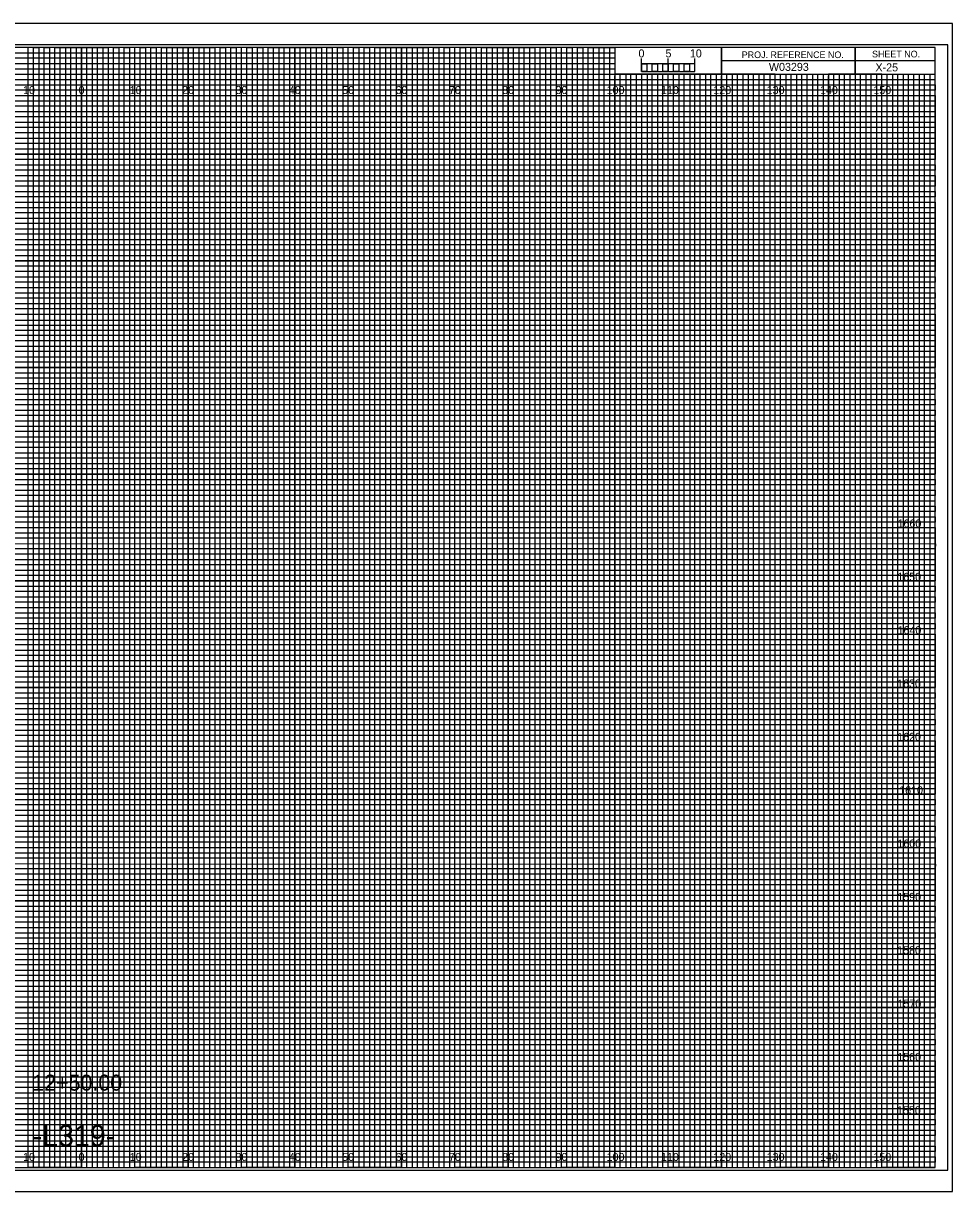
# Model space of a CAD drawing. Extents: x -13 to 323, y 215 to 434.
# Drawn here: x 149.1 to 323.3, y 215.5 to 434.5 of the extents above; entities that cross this region are included whole.
import ezdxf

# ---------------------------------------------------------------- set-up
doc = ezdxf.new("R2010")
doc.units = 0
for name, color, linetype in [('Exist Cross Section Cell', 7, 'Continuous'), ('Exist XS Center Line Elevation Label', 7, 'Continuous'), ('Exist XS Ground Line', 7, 'Continuous'), ('Prop XS EOT Tick Mark', 7, 'Continuous'), ('Prop XS Finish Grade', 7, 'Continuous'), ('Prop XS Finish Grade Earthwork', 7, 'Continuous'), ('Prop XS Finish Grade Pavement', 7, 'Continuous'), ('Prop XS Pvmt Edge Slope', 7, 'Continuous'), ('Prop XS SE Text', 7, 'Continuous'), ('Prop XS Side Slope Text', 7, 'Continuous'), ('Prop XS SS Elevation Text', 7, 'Continuous'), ('Prop XS Subgrade Earthwork', 7, 'Continuous'), ('Prop XSC Text', 7, 'Continuous'), ('Scratch_Level_5', 7, 'Continuous'), ('Typical Curb CELL', 7, 'Continuous'), ('Typical Guardrail CELL', 7, 'Continuous')]:
    doc.layers.add(name, color=color, linetype=linetype)

msp = doc.modelspace()

# ---------------------------------------------------------------- linework, layer by layer
at = {"layer": 'Exist Cross Section Cell'}
for points in [[(145, 220), (155, 220), (155, 430), (165, 430), (165, 220), (175, 220), (175, 430), (185, 430), (185, 220), (195, 220), (195, 430), (205, 430), (205, 220), (215, 220), (215, 430), (225, 430), (225, 220), (235, 220), (235, 430), (245, 430), (245, 220), (255, 220), (255, 430), (259.93, 430), (260, 430), (260, 425), (264.99, 425), (264.99, 220), (275, 220), (275, 425), (285, 425), (285, 220), (295, 220), (295, 425), (305, 425), (305, 220), (315, 220), (315, 425)], [(0, 425), (275, 425)], [(0, 405), (320, 405), (320, 415), (0, 415)], [(0, 385), (320, 385), (320, 395), (0, 395)], [(0, 365), (320, 365), (320, 375), (0, 375)], [(0, 345), (320, 345), (320, 355), (0, 355)], [(0, 325), (320, 325), (320, 335), (0, 335)], [(0, 305), (320, 305), (320, 315), (0, 315)], [(0, 285), (320, 285), (320, 295), (0, 295)], [(0, 265), (320, 265), (320, 275), (0, 275)], [(0, 245), (320, 245), (320, 255), (0, 255)], [(0, 225), (320, 225), (320, 235), (0, 235)]]:
    msp.add_lwpolyline(points, dxfattribs=at)
at = {"layer": 'Exist XS Center Line Elevation Label'}
for p, q in [((150, 430), (140, 430)), ((150, 220), (150, 430)), ((170, 430), (160, 430)), ((160, 430), (160, 220)), ((170, 220), (170, 430)), ((190, 430), (180, 430)), ((180, 430), (180, 220)), ((190, 220), (190, 430)), ((210, 430), (200, 430)), ((200, 430), (200, 220)), ((210, 220), (210, 430)), ((230, 430), (220, 430)), ((220, 430), (220, 220)), ((230, 220), (230, 430)), ((250, 430), (240, 430)), ((240, 430), (240, 220)), ((250, 220), (250, 430)), ((260, 430), (260, 220)), ((270, 220), (270, 425)), ((290, 425), (280, 425)), ((280, 425), (280, 220)), ((290, 220), (290, 425)), ((310, 425), (300, 425)), ((300, 425), (300, 220)), ((310, 220), (310, 425)), ((160, 220), (150, 220)), ((180, 220), (170, 220)), ((200, 220), (190, 220)), ((220, 220), (210, 220)), ((240, 220), (230, 220)), ((260, 220), (250, 220)), ((280, 220), (270, 220)), ((300, 220), (290, 220)), ((320, 220), (310, 220)), ((320, 220), (320, 220))]:
    msp.add_line(p, q, dxfattribs=at)
for points in [[(0, 420), (320, 420), (320, 410), (0, 410)], [(0, 400), (320, 400), (320, 390), (0, 390)], [(0, 380), (320, 380), (320, 370), (0, 370)], [(0, 360), (320, 360), (320, 350), (0, 350)], [(0, 340), (320, 340), (320, 330), (0, 330)], [(0, 320), (320, 320), (320, 310), (0, 310)], [(0, 300), (320, 300), (320, 290), (0, 290)], [(0, 280), (320, 280), (320, 270), (0, 270)], [(0, 260), (320, 260), (320, 250), (0, 250)], [(0, 240), (320, 240), (320, 230), (0, 230)]]:
    msp.add_lwpolyline(points, dxfattribs=at)
at = {"layer": 'Prop XS Finish Grade'}
msp.add_lwpolyline([(-10.8, 219.5), (322.4, 219.5), (322.4, 430.5), (-10.8, 430.5)], close=True, dxfattribs=at)
at = {"layer": 'Prop XS Finish Grade Earthwork'}
for p, q in [((150, 220), (150, 430)), ((160, 220), (160, 430)), ((170, 220), (170, 430)), ((180, 220), (180, 430)), ((190, 220), (190, 430)), ((200, 220), (200, 430)), ((210, 220), (210, 430)), ((220, 220), (220, 430)), ((230, 220), (230, 430)), ((240, 220), (240, 430)), ((250, 220), (250, 430)), ((260, 220), (260, 424.69)), ((270, 220), (270, 424.69)), ((280, 220), (280, 424.69)), ((290, 220), (290, 424.69)), ((300, 220), (300, 424.69)), ((310, 220), (310, 424.69)), ((0, 420), (320, 420)), ((0, 410), (320, 410)), ((0, 400), (320, 400)), ((0, 390), (320, 390)), ((0, 380), (320, 380)), ((0, 370), (320, 370)), ((0, 360), (320, 360)), ((0, 350), (320, 350)), ((0, 340), (320, 340)), ((0, 330), (320, 330)), ((0, 320), (320, 320)), ((0, 310), (320, 310)), ((0, 300), (320, 300)), ((0, 290), (320, 290)), ((0, 280), (320, 280)), ((0, 270), (320, 270)), ((0, 260), (320, 260)), ((0, 250), (320, 250)), ((0, 240), (320, 240)), ((0, 230), (320, 230))]:
    msp.add_line(p, q, dxfattribs=at)
at = {"layer": 'Prop XS Finish Grade Pavement'}
for p, q in [((267, 425), (266.01, 425)), ((266.01, 425), (266.01, 220)), ((267, 220), (267, 425)), ((269, 425), (268, 425)), ((268, 425), (268, 220)), ((269, 220), (269, 425)), ((266.01, 220), (265, 220)), ((268, 220), (267, 220))]:
    msp.add_line(p, q, dxfattribs=at)
for points in [[(150, 220), (151, 220), (151, 430), (152, 430), (152, 220)], [(152, 220), (153, 220), (153, 430), (154, 430), (154, 220)], [(155, 220), (156, 220), (156, 430), (157, 430), (157, 220)], [(157, 220), (158, 220), (158, 430), (159, 430), (159, 220)], [(160, 220), (161, 220), (161, 430), (162, 430), (162, 220)], [(162, 220), (163, 220), (163, 430), (164, 430), (164, 220)], [(165, 220), (166, 220), (166, 430), (167, 430), (167, 220)], [(167, 220), (168, 220), (168, 430), (169, 430), (169, 220)], [(170, 220), (171, 220), (171, 430), (172, 430), (172, 220)], [(172, 220), (173, 220), (173, 430), (174, 430), (174, 220)], [(175, 220), (176, 220), (176, 430), (177, 430), (177, 220)], [(177, 220), (178, 220), (178, 430), (179, 430), (179, 220)], [(180, 220), (181, 220), (181, 430), (182, 430), (182, 220)], [(182, 220), (183, 220), (183, 430), (184, 430), (184, 220)], [(185, 220), (186, 220), (186, 430), (187, 430), (187, 220)], [(187, 220), (188, 220), (188, 430), (189, 430), (189, 220)], [(190, 220), (191, 220), (191, 430), (192, 430), (192, 220)], [(192, 220), (193, 220), (193, 430), (194, 430), (194, 220)], [(195, 220), (196, 220), (196, 430), (197, 430), (197, 220)], [(197, 220), (198, 220), (198, 430), (199, 430), (199, 220)], [(200, 220), (201, 220), (201, 430), (202, 430), (202, 220)], [(202, 220), (203, 220), (203, 430), (204, 430), (204, 220)], [(205, 220), (206, 220), (206, 430), (207, 430), (207, 220)], [(207, 220), (208, 220), (208, 430), (209, 430), (209, 220)], [(210, 220), (211, 220), (211, 430), (212, 430), (212, 220)], [(212, 220), (213, 220), (213, 430), (214, 430), (214, 220)], [(215, 220), (216, 220), (216, 430), (217, 430), (217, 220)], [(217, 220), (218, 220), (218, 430), (219, 430), (219, 220)], [(220, 220), (221, 220), (221, 430), (222, 430), (222, 220)], [(222, 220), (223, 220), (223, 430), (224, 430), (224, 220)], [(225, 220), (226, 220), (226, 430), (227, 430), (227, 220)], [(227, 220), (228, 220), (228, 430), (229, 430), (229, 220)], [(230, 220), (231, 220), (231, 430), (232, 430), (232, 220)], [(232, 220), (233, 220), (233, 430), (234, 430), (234, 220)], [(235, 220), (236, 220), (236, 430), (237, 430), (237, 220)], [(237, 220), (238, 220), (238, 430), (239, 430), (239, 220)], [(240, 220), (241, 220), (241, 430), (242, 430), (242, 220)], [(242, 220), (243, 220), (243, 430), (244, 430), (244, 220)], [(245, 220), (246, 220), (246, 430), (247, 430), (247, 220)], [(247, 220), (248, 220), (248, 430), (249, 430), (249, 220)], [(250, 220), (251, 220), (251, 430), (252, 430), (252, 220)], [(252, 220), (253, 220), (253, 430), (254, 430), (254, 220)], [(255, 220), (256, 220), (256, 430), (257, 430), (257, 220)], [(257, 220), (258, 220), (258, 430), (259, 430), (259, 220)], [(260, 220), (261, 220), (261, 425), (262.02, 425), (262.02, 220)], [(262, 220), (263, 220), (263, 425), (263.99, 425), (263.99, 220)], [(270, 220), (270.98, 220), (270.98, 425), (272, 425), (272, 220)], [(272, 220), (273, 220), (273, 425), (274.05, 425), (274.05, 220)], [(275, 220), (276, 220), (276, 425), (277, 425), (277, 220)], [(277, 220), (278, 220), (278, 425), (279, 425), (279, 220)], [(280, 220), (281, 220), (281, 425), (282, 425), (282, 220)], [(282, 220), (283, 220), (283, 425), (284, 425), (284, 220)], [(285, 220), (286, 220), (286, 425), (287, 425), (287, 220)], [(287, 220), (288, 220), (288, 425), (289, 425), (289, 220)], [(290, 220), (291, 220), (291, 425), (292, 425), (292, 220)], [(292, 220), (293, 220), (293, 425), (294, 425), (294, 220)], [(295, 220), (296, 220), (296, 425), (297, 425), (297, 220)], [(297, 220), (298, 220), (298, 425), (299, 425), (299, 220)], [(300, 220), (301, 220), (301, 425), (302, 425), (302, 220)], [(302, 220), (303, 220), (303, 425), (304, 425), (304, 220)], [(305, 220), (306, 220), (306, 425), (307, 425), (307, 220)], [(307, 220), (308, 220), (308, 425), (309, 425), (309, 220)], [(310, 220), (311, 220), (311, 425), (312, 425), (312, 220)], [(312, 220), (313, 220), (313, 425), (314, 425), (314, 220)], [(315, 220), (316, 220), (316, 425), (317, 425), (317, 220)], [(317, 220), (318, 220), (318, 425), (319, 425), (319, 220)]]:
    msp.add_lwpolyline(points, dxfattribs=at)
at = {"layer": 'Prop XS SE Text'}
for p, q in [((305, 430), (305, 425)), ((305, 425), (305, 430)), ((280, 427.5), (280, 425)), ((320, 427.49), (280, 427.49)), ((280, 425), (320, 425))]:
    msp.add_line(p, q, dxfattribs=at)
for points in [[(320, 430), (0, 430), (0, 220), (320, 220)], [(280, 430), (260, 430), (260, 425.03), (280, 425.03)], [(320, 430), (280, 430), (280, 425), (320, 425)]]:
    msp.add_lwpolyline(points, close=True, dxfattribs=at)
at = {"layer": 'Prop XS Subgrade Earthwork'}
for p, q in [((265, 425.49), (265, 427.9)), ((265, 426.9), (265, 427.9)), ((270, 425.49), (270, 427.9)), ((275, 425.49), (275, 427.9)), ((275, 426.9), (275, 427.9))]:
    msp.add_line(p, q, dxfattribs=at)
for points in [[(275, 426.9), (265, 426.9), (265, 425.49), (275, 425.49)], [(265, 426.9), (266, 426.9), (266, 425.49), (265, 425.49)], [(267, 426.9), (268, 426.9), (268, 425.49), (267, 425.49)], [(269, 426.9), (270, 426.9), (270, 425.49), (269, 425.49)], [(271, 426.9), (272, 426.9), (272, 425.49), (271, 425.49)], [(273, 426.9), (274, 426.9), (274, 425.49), (273, 425.49)]]:
    msp.add_lwpolyline(points, close=True, dxfattribs=at)
at = {"layer": 'Scratch_Level_5'}
for p, q in [((0, 429), (260, 429)), ((260, 427.98), (0, 427.98)), ((260, 429), (260, 427.98)), ((0, 427), (260, 427)), ((260, 425.89), (0, 425.89)), ((260, 427), (260, 425.89)), ((0, 424), (320, 424))]:
    msp.add_line(p, q, dxfattribs=at)
for points in [[(0, 423), (270, 423), (320, 423), (320, 422), (0, 422)], [(0, 421), (320, 421), (320, 419), (0, 419)], [(0, 418), (320, 418), (320, 417), (0, 416.98)], [(0, 416), (320, 416), (320, 414), (0, 414)], [(0, 413), (320, 413), (320, 412), (0, 412)], [(0, 411), (320, 411), (320, 409), (0, 409)], [(0, 408), (320, 408), (320, 407), (0, 407)], [(0, 406), (320, 406), (320, 404), (0, 404)], [(0, 403), (320, 403), (320, 402), (0, 402)], [(0, 401), (320, 401), (320, 399), (0, 399)], [(0, 398), (320, 398), (320, 397), (0, 397)], [(0, 396), (320, 396), (320, 393.95), (320, 393), (320, 392), (0, 392)], [(0, 394), (320, 394), (320, 393), (0, 393)], [(0, 391), (320, 391), (320, 389), (0, 389.03)], [(0, 389.03), (320, 389), (320, 388), (0, 388)], [(0, 387), (320, 387), (320, 386), (0, 386)], [(0, 384), (320, 384), (320, 383), (0, 383)], [(0, 382), (320, 382), (320, 381), (0, 381)], [(-0.07, 378.89), (320, 378.89), (320, 377.88), (-0.07, 377.88)], [(0, 377), (320, 377), (320, 376), (0, 376)], [(0, 374), (320, 374), (320, 373), (0, 373)], [(0, 372), (320, 372), (320, 371), (0, 371)], [(0, 369), (320, 369), (320, 368), (0, 368)], [(0, 367), (320, 367), (320, 366), (0, 366)], [(0, 364), (320, 364), (320, 363), (0, 363)], [(0, 362), (320, 362), (320, 361), (0, 361)], [(0, 359), (320, 359), (319.99, 357.98), (0, 358)], [(0, 357), (320, 357), (320, 356), (0, 356)], [(0, 354), (320, 354), (320, 353), (0, 353)], [(0, 352), (320, 352), (320, 351), (0, 351)], [(0, 349), (320, 349), (320, 348), (0, 348)], [(0, 347), (320, 347), (320, 346), (0, 346)], [(0, 344), (320, 344), (320, 343), (0, 343)], [(0, 342), (320, 342), (320, 341), (0, 341)], [(0, 339), (320, 339), (320, 338), (0, 338)], [(0, 336.99), (320.07, 336.91), (320, 336), (0, 336)], [(0, 334), (320, 334), (320, 333), (0, 333)], [(0, 332), (320, 332), (320, 331), (0, 331)], [(0, 329), (320, 329), (320, 328), (0, 328)], [(0, 327), (320, 327), (320, 326), (0, 326)], [(0, 324), (320, 324), (320, 323), (0, 323)], [(0, 322), (320, 322), (320, 321), (0, 321)], [(0, 319), (320, 319), (320, 318), (0, 318)], [(0, 317), (320, 317), (320, 316), (0, 316)], [(0, 314), (320, 314), (320, 313), (0, 313)], [(0, 312), (320, 312), (320, 311), (0, 311)], [(0, 309), (320, 309), (320, 308), (0, 308)], [(0, 307), (320, 307), (320, 306), (0, 306)], [(0, 304), (320, 304), (320, 303), (0, 303)], [(0, 302), (320, 302), (320, 301), (0, 301)], [(0, 299), (320, 299), (319.99, 297.98), (0, 298)], [(0, 297), (320, 297), (320, 296), (0, 296)], [(0, 294), (320, 294), (320, 293), (0, 293)], [(0, 292), (320, 292), (320, 291), (0, 291)], [(0, 289), (320, 289), (320, 288), (0, 288)], [(0, 287), (320, 287), (320, 286), (0, 286)], [(0, 284), (320, 284), (320, 283), (0, 283)], [(0, 282), (320, 282), (320, 281), (0, 281)], [(0, 279), (320, 279), (320, 278), (0, 278)], [(0, 276.99), (320.07, 276.91), (320, 276), (0, 276)], [(0, 274), (320, 274), (320, 273), (0, 273)], [(0, 272), (320, 272), (320, 271), (0, 271)], [(0, 269), (320, 269), (320, 268), (0, 268)], [(0, 267), (320, 267), (320, 266), (0, 266)], [(0, 264), (320, 264), (320, 263), (0, 263)], [(0, 262), (320, 262), (320, 261), (0, 261)], [(0, 259), (320, 259), (320, 258), (0, 258)], [(0, 257), (320, 257), (320, 256), (0, 256)], [(0, 254), (320, 254), (320, 253), (0, 253)], [(0, 252), (320, 252), (320, 251), (0, 251)], [(0, 249), (320, 249), (320, 248), (0, 248)], [(0, 247), (320, 247), (320, 246), (0, 246)], [(0, 244), (320, 244), (320, 243), (0, 243)], [(0, 242), (320, 242), (320, 241), (0, 241)], [(0, 239), (320, 239), (320, 238), (0, 238)], [(0, 237), (320, 237), (320, 236), (0, 236)], [(0, 234), (320, 234), (320, 233), (0, 233)], [(0, 232), (320, 232), (320, 231), (0, 231)], [(0, 229), (320, 229), (320, 228), (0, 228)], [(0, 227), (320, 227), (320, 226), (0, 226)], [(0, 224), (320, 224), (320, 223), (0, 223)], [(0, 222), (320, 222), (320, 221), (0, 221)]]:
    msp.add_lwpolyline(points, dxfattribs=at)
at = {"layer": 'Typical Curb CELL'}
msp.add_lwpolyline([(-13.4, 215.5), (323.3, 215.5), (323.3, 434.5), (-13.4, 434.5)], close=True, dxfattribs=at)
at = {"layer": 'Typical Guardrail CELL'}
for p, q in [((323.3, 434.5), (-13.4, 434.5)), ((-13.4, 215.5), (323.3, 215.5))]:
    msp.add_line(p, q, dxfattribs=at)

# ---------------------------------------------------------------- texts
at = {"layer": 'Exist XS Ground Line'}
for s, p in [('10', (149.04, 421.25)), ('0', (159.45, 421.25)), ('0', (159.45, 421.25)), ('10', (169.04, 421.25)), ('20', (178.86, 421.25)), ('30', (188.86, 421.25)), ('40', (198.86, 421.25)), ('50', (208.86, 421.25)), ('60', (218.86, 421.25)), ('70', (228.86, 421.25)), ('80', (238.86, 421.25)), ('90', (248.86, 421.25)), ('100', (258.44, 421.25)), ('110', (268.62, 421.25)), ('120', (278.44, 421.25)), ('130', (288.44, 421.25)), ('140', (298.44, 421.25)), ('150', (308.44, 421.25)), ('10', (149.04, 221.25)), ('0', (159.45, 221.25)), ('0', (159.45, 221.25)), ('10', (169.04, 221.25)), ('20', (178.86, 221.25)), ('30', (188.86, 221.25)), ('40', (198.86, 221.25)), ('50', (208.86, 221.25)), ('60', (218.86, 221.25)), ('70', (228.86, 221.25)), ('80', (238.86, 221.25)), ('90', (248.86, 221.25)), ('100', (258.44, 221.25)), ('110', (268.62, 221.25)), ('120', (278.44, 221.25)), ('130', (288.44, 221.25)), ('140', (298.44, 221.25)), ('150', (308.44, 221.25))]:
    msp.add_text(s, height=1.5, dxfattribs=at).set_placement(p)
at = {"layer": 'Prop XS EOT Tick Mark'}
msp.add_text('-L319-', height=4, dxfattribs=at).set_placement((150.84, 224))
at = {"layer": 'Prop XS Pvmt Edge Slope'}
for s, p in [('5', (269.47, 428.12)), ('10', (274.04, 428.12))]:
    msp.add_text(s, height=1.5, dxfattribs=at).set_placement(p)
at = {"layer": 'Prop XS SE Text'}
for s, p in [('PROJ. REFERENCE NO.', (283.77, 427.99)), ('SHEET NO.', (308.19, 428.12))]:
    msp.add_text(s, height=1.25, dxfattribs=at).set_placement(p)
at = {"layer": 'Prop XS Side Slope Text'}
for s, p in [('1660', (312.97, 340)), ('1650', (312.92, 330)), ('1640', (312.97, 320)), ('1630', (312.89, 310)), ('1620', (312.9, 300)), ('1610', (313.28, 290)), ('1600', (312.95, 280)), ('1590', (312.92, 270)), ('1580', (312.9, 260)), ('1570', (312.96, 250)), ('1560', (312.92, 240)), ('1550', (312.87, 230))]:
    msp.add_text(s, height=1.5, dxfattribs=at).set_placement(p)
at = {"layer": 'Prop XS SS Elevation Text'}
msp.add_text('12+50.00', height=3, dxfattribs=at).set_placement((150.77, 234.43))
at = {"layer": 'Prop XS Subgrade Earthwork'}
msp.add_text('0', height=1.5, dxfattribs=at).set_placement((264.41, 428.12))
at = {"layer": 'Prop XSC Text'}
for s, p in [('W03293', (288.86, 425.59)), ('X-25', (308.83, 425.5))]:
    msp.add_text(s, height=1.5, dxfattribs=at).set_placement(p)

doc.saveas('drawing.dxf')
